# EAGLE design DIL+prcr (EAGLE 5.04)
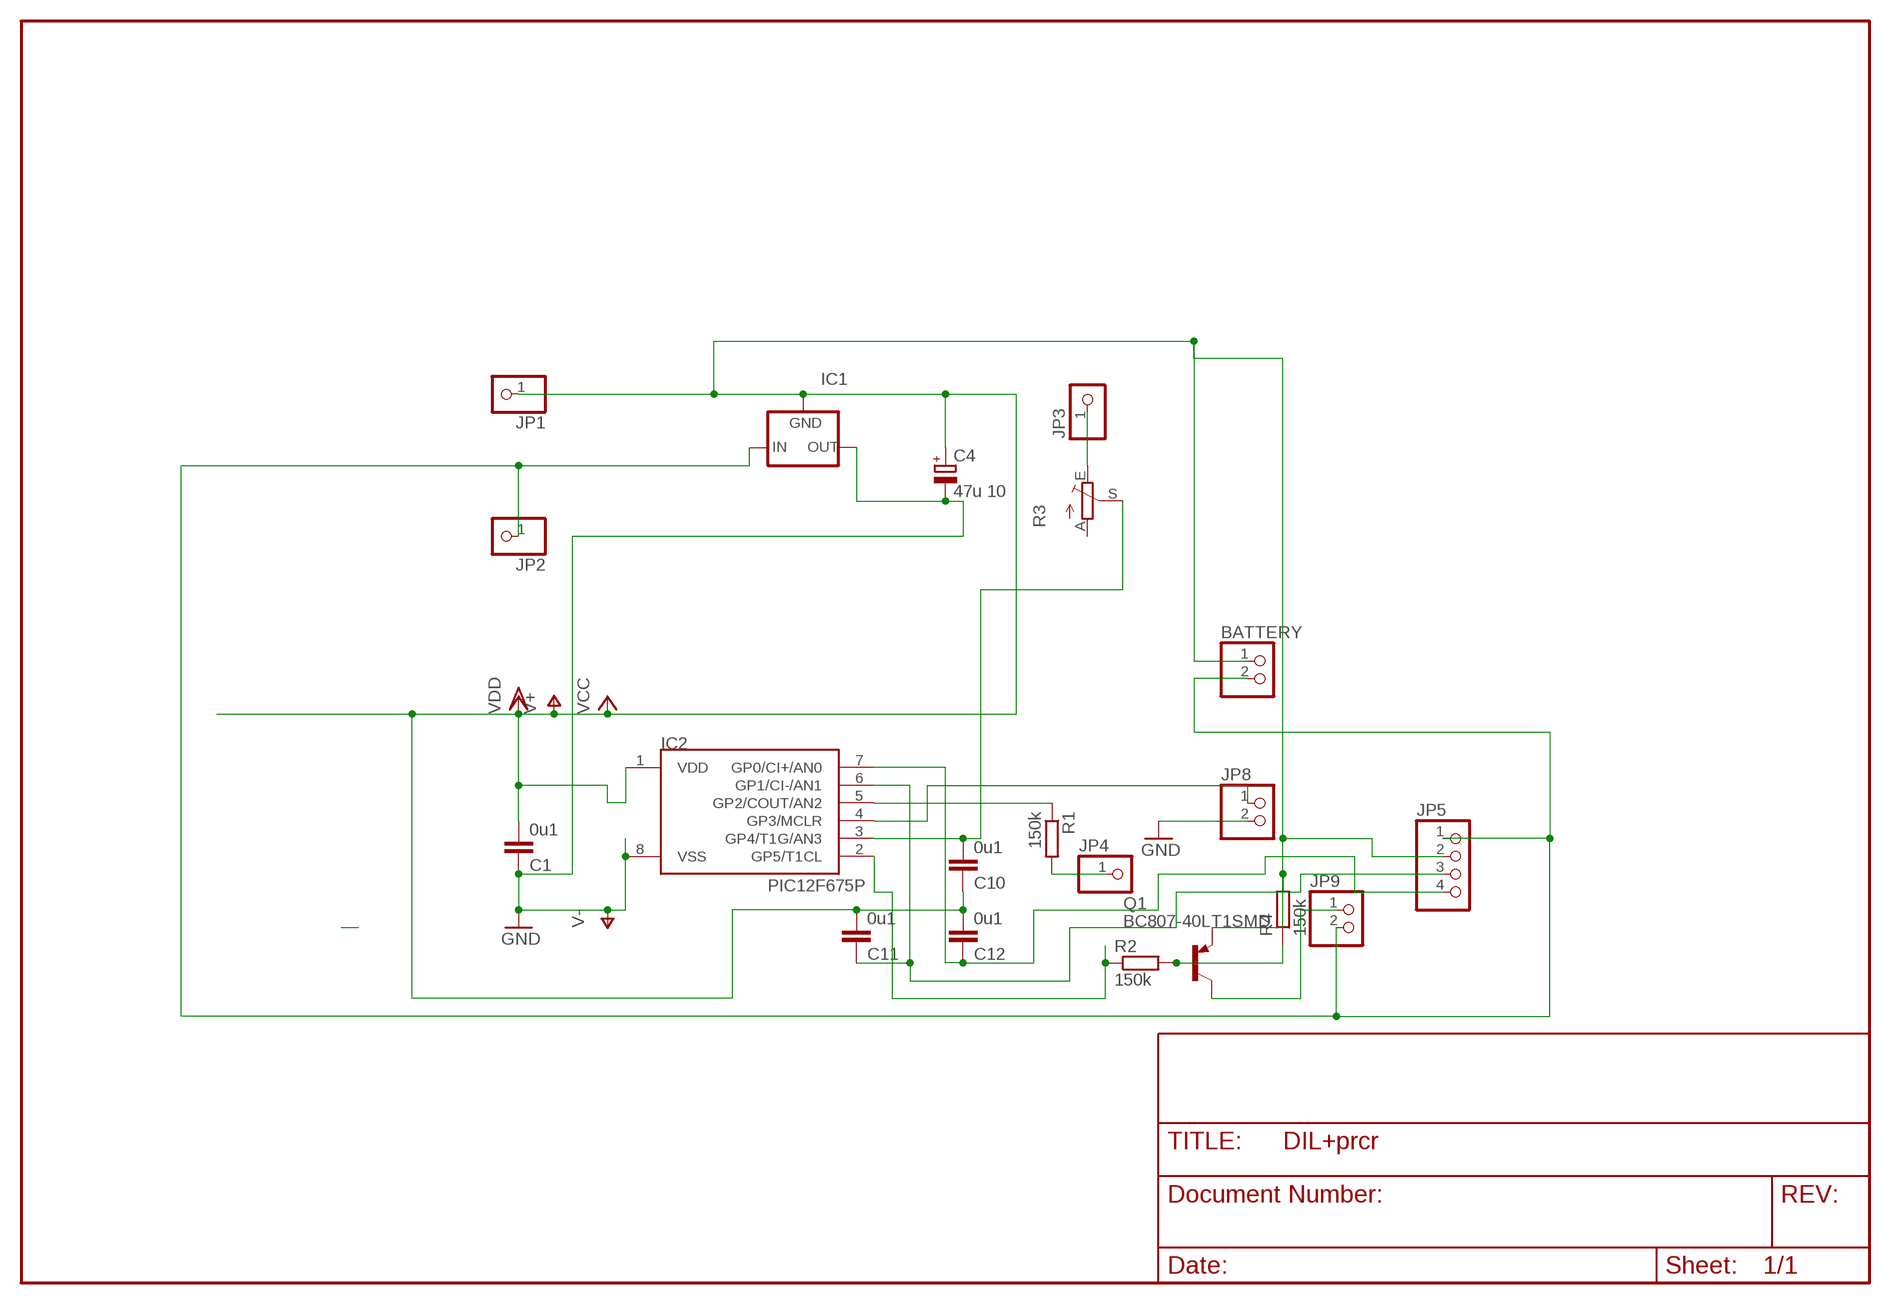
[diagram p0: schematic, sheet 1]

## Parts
BATTERY  PINHD-1X2  [1X02]
C1  0u1  C-EUC1206  [C1206]
C4  47u 10  CPOL-EUE2.5-6  [E2,5-6]
C10  0u1  C-EUC1206  [C1206]
C11  0u1  C-EUC1206  [C1206]
C12  0u1  C-EUC1206  [C1206]
IC1  79LXX  [79LXX]
IC2  PIC12F675P  [DIL8]
JP1  PINHD-1X1  [1X01]
JP2  PINHD-1X1  [1X01]
JP3  PINHD-1X1  [1X01]
JP4  PINHD-1X1  [1X01]
JP5  PINHD-1X4  [1X04]
JP8  PINHD-1X2  [1X02]
JP9  PINHD-1X2  [1X02]
Q1  BC807-40LT1SMD  [SOT23-BEC]
R1  150k  R-EU_R0805  [R0805]
R2  150k  R-EU_R0805  [R0805]
R3  TRIM_EU-CA6V  [CA6V]
R4  150k  R-EU_R0805  [R0805]

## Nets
GND: C1.1 C4.- IC1.OUT IC2.8(VSS) JP8.2 ; supply symbol labelled V-
N$1: JP3.1 R3.E
N$2: JP4.1 R1.2
N$3: IC2.4(GP3/MCLR) JP8.1
N$4: Q1.B R2.2 R4.1
N$5: IC2.5(GP2/COUT/AN2) R1.1
N$7: BATTERY.2 IC1.IN JP2.1 JP5.1 JP9.2
N$8: IC2.2(GP5/T1CL) R2.1
N$9: JP9.1 Q1.C
N$12: C10.2 IC2.3(GP4/T1G/AN3) R3.S
N$13: C12.1 IC2.7(GP0/CI+/AN0) JP5.4
N$15: C11.1 IC2.6(GP1/CI-/AN1) JP5.3
V+: BATTERY.1 C1.2 C4.+ C10.1 C11.2 C12.2 IC1.GND IC2.1(VDD) JP1.1 JP5.2 Q1.E R4.2 ; supply symbol labelled VCC, VDD
Unconnected: R3.A

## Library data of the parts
BATTERY JP8 JP9 = pinhead:PINHD-1X2: PIN HEADER
C1 C10-C12 = rcl:C-EU: CAPACITOR, European symbol
C4 = rcl:CPOL-EU: POLARIZED CAPACITOR, European symbol
IC1 = v-reg:79LXX: VOLTAGE REGULATOR
IC2 = microchip-3:PIC12F6*: uPC nW 1k Program Flash memory 2x Timer Comparator 10b A/D converter/ 4xIN
JP1-JP4 = pinhead:PINHD-1X1: PIN HEADER
JP5 = pinhead(2):PINHD-1X4: PIN HEADER
Q1 = transistor-pnp:BC807*: PNP Transistror
R1 R2 R4 = rcl:R-EU_: RESISTOR, European symbol
R3 = pot:TRIM_EU-: POTENTIOMETER

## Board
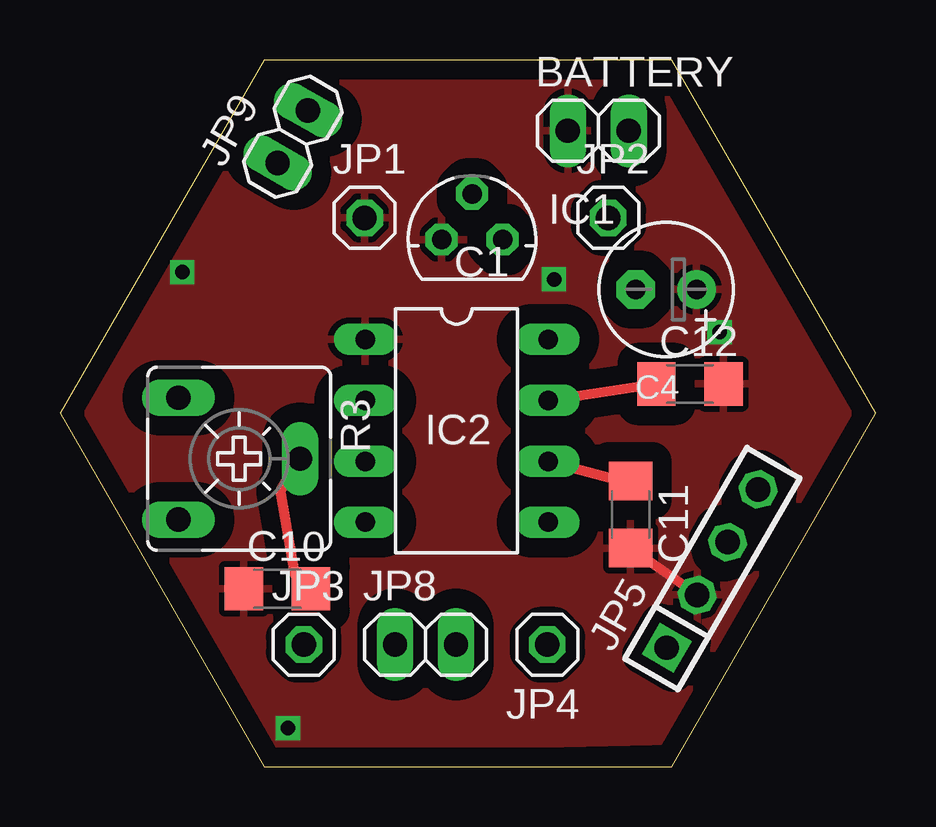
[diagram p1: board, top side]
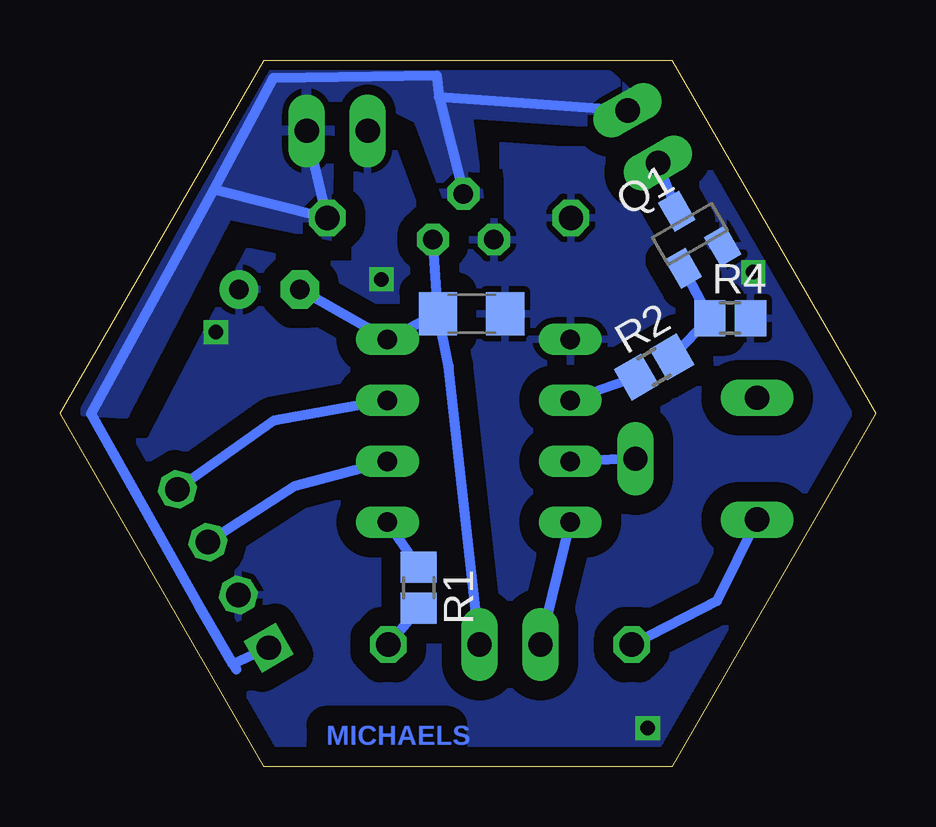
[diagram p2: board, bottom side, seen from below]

Size 34 x 29.44 mm. Coordinates in mm from the lower left corner, seen from the top.
Outline: 8.5,0 25.5,0 34,14.72 25.5,29.44 8.5,29.44 0,14.72 8.5,0
Copper layers (1*16): Top 0.035mm / dielectric 1.5mm / Bottom 0.035mm
Design rules "default *": minimum track width 10mil, minimum drill 24mil, track to track 8mil, track to pad 8mil, pad to pad 8mil, via to via 8mil, smd to smd 8mil, copper to edge 10mil, drill to drill 8mil, minimum pad ring 10mil, minimum via ring 8mil, stop-mask expansion 4mil, vias tented up to drill 0mil, thermal gap 10mil

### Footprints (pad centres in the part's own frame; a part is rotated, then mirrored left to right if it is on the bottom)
1X02 = drill 1.016 long: 1 -1.27,0; 2 1.27,0
C1206 = smd 1.6 x 1.8: 1 -1.4,0; 2 1.4,0
E2,5-6 = drill 0.813 pad 1.6 round: + -1.27,0 | drill 0.813 pad 1.6 octagon: - 1.27,0
79LXX = drill 0.813 octagon: GND -1.27,0; IN 0,1.905; OUT 1.27,0
DIL8 = drill 0.813 long: 1 -3.81,-3.81; 2 -1.27,-3.81; 3 1.27,-3.81; 4 3.81,-3.81; 5 3.81,3.81; 6 1.27,3.81; 7 -1.27,3.81; 8 -3.81,3.81
1X01 = drill 1.016 octagon: 1 0,0
1X04 = drill 1.016 square: 1 -3.81,0 | drill 1.016 octagon: 2 -1.27,0; 3 1.27,0; 4 3.81,0
SOT23-BEC = smd 1 x 1.4: B -0.95,-1.1; C 0,1.1; E 0.95,-1.1
R0805 = smd 1.3 x 1.5: 1 -0.85,0; 2 0.85,0
CA6V = drill 1.016 long: A -2.54,-2.54; E 2.54,-2.54; S 0,2.54

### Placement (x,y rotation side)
BATTERY  22.44,26.49 0 top
C1  16.84,18.86 0 bottom
C4  25.27,19.88 180 top
C10  9.07,7.41 0 top
C11  23.79,10.5 270 top
C12  26.26,15.94 0 top
IC1  17.18,21.96 0 top
IC2  16.54,13.99 270 top
JP1  12.7,22.86 0 top
JP2  22.86,22.86 0 top
JP3  10.16,5.08 0 top
JP4  20.32,5.08 180 top
JP5  27.2,8.25 60 top
JP8  15.24,5.08 0 top
JP9  9.71,26.24 60 top
Q1  7.74,22.18 30 bottom
R1  19.05,7.45 270 bottom
R2  9.23,16.65 30 bottom
R3  7.47,12.83 270 top
R4  6.06,18.69 0 bottom

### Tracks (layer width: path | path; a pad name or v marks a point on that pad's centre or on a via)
GND
  Bottom 0.406: JP8.2 17.8,16.7 C1.1 | C1.1 IC2.8 C4.- | C1.1 IC1.OUT
N$1
  Bottom 0.406: JP3.1 6.6,6.9 R3.E
N$2
  Bottom 0.406: R1.2 JP4.1
N$3
  Bottom 0.406: JP8.1 IC2.4
N$4
  Bottom 0.406: Q1.B R4.1 R2.2
N$5
  Bottom 0.406: R1.1 IC2.5
N$7
  Bottom 0.406: 26.78,4.27 26.65,4.05 | 26.78,4.27 28.2,6.7 32.7,14.7 27.58,24.05 | 27.58,24.05 25.1,28.7 18.3,28.8 18.2,27.9 | 18.2,27.9 IC1.IN | 18.2,27.9 JP9.2 | 27.58,24.05 JP2.1 BATTERY.2 | JP5.1 26.78,4.27
  pour Bottom (isolate 0.406, rank 2): 10.16,27.94 11.1,28.8 25.2,29 33,14.8 31.3,14.7 27,23 22.6,22.1 22.8,24.1 22.7,27.9 20.9,27.9 19.1,27 17.8,23.5 16.5,23.5 17,27.2 11.3,26.8
N$8
  Bottom 0.406: R2.1 IC2.2
N$9
  Bottom 0.406: JP9.1 Q1.C
N$12
  Top 0.406: R3.S 9.2,11.5 9.8,8 C10.2
  Bottom 0.406: R3.S IC2.3
N$13
  Top 0.406: IC2.7 C12.1
  Bottom 0.406: JP5.4 25.1,14.4 IC2.7
N$15
  Top 0.406: C11.1 23.33,11.93 IC2.6
  Bottom 0.406: JP5.3 24.2,11.7 IC2.6
V+  (via drill 0.6)
  Top 0.406: JP5.2 C11.2
  other vias: 20.6,20.3 5.1,20.6 9.5,1.6 27.5,18.1
  pour Bottom (isolate 0.813, rank 4): 25.09,0.65 6.94,0.85 -0.63,14.71 7.94,28.25 23.9,28.98 28.25,24.24 33.14,13.91
  pour Top (isolate 0.813, rank 4): 25.05,28.74 33.52,14.83 25.59,1.05 7.24,0.65 -0.28,14.57 9.11,28.44

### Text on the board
Bottom: MICHAELS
